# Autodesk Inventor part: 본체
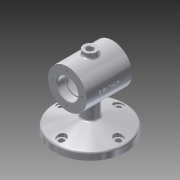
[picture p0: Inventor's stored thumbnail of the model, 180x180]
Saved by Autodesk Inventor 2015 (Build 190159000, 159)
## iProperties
Created: 2018-12
Part Number: 본체
Material: 알루미늄 6061
Document SubType Name: Modeling
Designer: now060
Density: 2.7 g/cm^3
Appearance: 알루미늄 - 평지
Mass: 685.037 g
Surface Area: 554.996 cm^2
Volume: 253.717 cm^3
Author: now060
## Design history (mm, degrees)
sketch "스케치7"
  geometry: C1 r 55 at (0, 0); 1 further point
  constraints: 1 centre point, 1 coincident
  dimensions: "d19" = 110 diameter of C1
extrude "돌출2" new body sketch "스케치7" distance "d20" = 11; taper "d21" = 0 deg
sketch "스케치8"
  geometry: C1 r 55 at (0, 0) reference; C2 r 12 at (0, 0)
  constraints: 1 centre point, 1 coincident
  dimensions: "d22" = 24 diameter of C2
extrude "돌출3" join sketch "스케치8" distance "d23" = 65; taper "d24" = 0 deg
sketch "스케치9"
  geometry: L1 (55, 11)-(55, 0) reference; L2 (55, 0)-(-55, 0) reference; L3 (-55, 0)-(-55, 11) reference; L4 (-55, 11)-(-12, 11) reference; L5 (-12, 11)-(-12, 76) reference; L6 (-12, 76)-(12, 76) reference; L7 (12, 76)-(12, 11) reference; L8 (12, 11)-(55, 11) reference; L9 (-35, 75)-(35, 75); L10 (35, 75)-(35, 105); L11 (35, 105)-(-35, 105); L12 (-35, 105)-(-35, 75); 3 further points
  constraints: 8 end point, 3 perpendicular, 2 midpoint, 1 horizontal, 1 vertical alignment
  dimensions: "d25" = 30 distance of L9.end L10.end; "d26" = 70 distance of L10.end L11.end; "d27" = 75 distance from line of L9 point (0, 0)
revolve "회전5" sketch "스케치9" stored, may be unused: angle "d28" = 90 deg
sketch "스케치10"
  geometry: L1 (55, 11)-(55, 0) reference; L2 (55, 0)-(-55, 0) reference; L3 (-55, 0)-(-55, 11) reference; L4 (-55, 11)-(-12, 11) reference; L5 (-12, 11)-(-12, 45) reference; L6 (-12, 45)-(-35, 45) reference; L7 (-35, 45)-(-35, 105) reference; L8 (-35, 105)-(35, 105) reference; L9 (35, 105)-(35, 45) reference; L10 (35, 45)-(12, 45) reference; L11 (12, 45)-(12, 11) reference; L12 (12, 11)-(55, 11) reference; L13 (-35, 45)-(-35, 105) reference; L14 (-35, 75)-(-23, 75); L15 (-23, 75)-(-23, 90.7); L16 (-23.3, 91)-(-35, 91); L17 (-35, 91)-(-35, 75); A1 r 0.3 centre (-23.3, 90.7) between (-23, 90.7) and (-23.3, 91); 2 further points
  constraints: 8 end point, 2 parallel, 2 point on circle, 2 point on line, 2 tangent, 1 centre point, 1 horizontal, 1 midpoint, 1 perpendicular
  dimensions: "d29" = 12 distance of point (-23, 91) L16.end; "d30" = 16 distance of L14.end point (-23, 91); "d31" = 0.3 radius of A1
revolve "회전6" sketch "스케치10" stored, may be unused: angle "d32" = 90 deg
sketch "스케치11"
  geometry: L1 (55, 11)-(55, 0) reference; L2 (55, 0)-(-55, 0) reference; L3 (-55, 0)-(-55, 11) reference; L4 (-55, 11)-(-12, 11) reference; L5 (-12, 11)-(-12, 45) reference; L6 (-12, 45)-(-35, 45) reference; L7 (-35, 45)-(-35, 59) reference; L8 (-35, 59)-(-23.3, 59) reference; L9 (-23, 59.3)-(-23, 90.7) reference; L10 (-23.3, 91)-(-35, 91) reference; L11 (-35, 91)-(-35, 105) reference; L12 (-35, 105)-(35, 105) reference; L13 (35, 105)-(35, 45) reference; L14 (35, 45)-(12, 45) reference; L15 (12, 45)-(12, 11) reference; L16 (12, 11)-(55, 11) reference; L17 (-23, 75)-(-20, 75); L18 (-20, 75)-(-20, 89); L19 (-20, 89)-(-23, 89); L20 (-23, 89)-(-23, 75); A1 r 0.3 centre (-23.3, 59.3) between (-23.3, 59) and (-23, 59.3) reference; A2 r 0.3 centre (-23.3, 90.7) between (-23, 90.7) and (-23.3, 91) reference; 1 further point
  constraints: 8 end point, 2 parallel, 1 horizontal, 1 midpoint, 1 perpendicular
  dimensions: "d33" = 3 distance of L18.end L19.end; "d34" = 14 distance of L17.end L18.end
revolve "회전7" sketch "스케치11" stored, may be unused: angle "d35" = 90 deg
sketch "스케치12"
  geometry: L1 (55, 11)-(55, 0) reference; L2 (55, 0)-(-55, 0) reference; L3 (-55, 0)-(-55, 11) reference; L4 (-55, 11)-(-12, 11) reference; L5 (-12, 11)-(-12, 45) reference; L6 (-12, 45)-(-35, 45) reference; L7 (-35, 45)-(-35, 59) reference; L8 (-35, 59)-(-23.3, 59) reference; L9 (-23, 59.3)-(-23, 61) reference; L10 (-23, 61)-(-20, 61) reference; L11 (-20, 61)-(-20, 89) reference; L12 (-20, 89)-(-23, 89) reference; L13 (-23, 89)-(-23, 90.7) reference; L14 (-23.3, 91)-(-35, 91) reference; L15 (-35, 91)-(-35, 105) reference; L16 (-35, 105)-(35, 105) reference; L17 (35, 105)-(35, 45) reference; L18 (35, 45)-(12, 45) reference; L19 (12, 45)-(12, 11) reference; L20 (12, 11)-(55, 11) reference; L21 (-20, 75)-(20, 75); L22 (20, 75)-(20, 97); L23 (17, 100)-(-17, 100); L24 (-20, 97)-(-20, 75); A1 r 0.3 centre (-23.3, 59.3) between (-23.3, 59) and (-23, 59.3) reference; A2 r 0.3 centre (-23.3, 90.7) between (-23, 90.7) and (-23.3, 91) reference; A3 r 3 centre (-17, 97) between (-17, 100) and (-20, 97); A4 r 3 centre (17, 97) between (20, 97) and (17, 100); 3 further points
  constraints: 8 end point, 4 point on circle, 4 point on line, 4 tangent, 2 centre point, 2 parallel, 1 equal radius, 1 horizontal, 1 midpoint, 1 perpendicular
  dimensions: "d36" = 40 distance of point (20, 100) point (-20, 100); "d37" = 25 distance of L21.end point (20, 100); "d38" = 3 radius of A3
revolve "회전8" sketch "스케치12" stored, may be unused: angle "d39" = 90 deg
sketch "스케치13"
  geometry: L1 (55, 11)-(55, 0) reference; L2 (55, 0)-(-55, 0) reference; L3 (-55, 0)-(-55, 11) reference; L4 (-55, 11)-(-12, 11) reference; L5 (-12, 11)-(-12, 45) reference; L6 (-12, 45)-(-35, 45) reference; L7 (-35, 45)-(-35, 59) reference; L8 (-35, 59)-(-23.3, 59) reference; L9 (-23, 59.3)-(-23, 61) reference; L10 (-23, 61)-(-20, 61) reference; L11 (-20, 61)-(-20, 53) reference; L12 (-17, 50)-(17, 50) reference; L13 (20, 53)-(20, 97) reference; L14 (17, 100)-(-17, 100) reference; L15 (-20, 97)-(-20, 89) reference; L16 (-20, 89)-(-23, 89) reference; L17 (-23, 89)-(-23, 90.7) reference; L18 (-23.3, 91)-(-35, 91) reference; L19 (-35, 91)-(-35, 105) reference; L20 (-35, 105)-(35, 105) reference; L21 (35, 105)-(35, 45) reference; L22 (35, 45)-(12, 45) reference; L23 (12, 45)-(12, 11) reference; L24 (12, 11)-(55, 11) reference; L25 (20, 75)-(23, 75); L26 (23, 75)-(23, 89); L27 (23, 89)-(20, 89); L28 (20, 89)-(20, 75); A1 r 0.3 centre (-23.3, 59.3) between (-23.3, 59) and (-23, 59.3) reference; A2 r 3 centre (-17, 53) between (-20, 53) and (-17, 50) reference; A3 r 3 centre (17, 53) between (17, 50) and (20, 53) reference; A4 r 3 centre (17, 97) between (20, 97) and (17, 100) reference; A5 r 3 centre (-17, 97) between (-17, 100) and (-20, 97) reference; A6 r 0.3 centre (-23.3, 90.7) between (-23, 90.7) and (-23.3, 91) reference; 1 further point
  constraints: 8 end point, 2 parallel, 1 horizontal, 1 midpoint, 1 perpendicular
  dimensions: "d40" = 3 distance of L26.end L27.end; "d41" = 14 distance of L25.end L26.end
revolve "회전9" sketch "스케치13" stored, may be unused: angle "d42" = 90 deg
sketch "스케치14"
  geometry: L1 (55, 11)-(55, 0) reference; L2 (55, 0)-(-55, 0) reference; L3 (-55, 0)-(-55, 11) reference; L4 (-55, 11)-(-12, 11) reference; L5 (-12, 11)-(-12, 45) reference; L6 (-12, 45)-(-35, 45) reference; L7 (-35, 45)-(-35, 59) reference; L8 (-35, 59)-(-23.3, 59) reference; L9 (-23, 59.3)-(-23, 61) reference; L10 (-23, 61)-(-20, 61) reference; L11 (-20, 61)-(-20, 53) reference; L12 (-17, 50)-(17, 50) reference; L13 (20, 53)-(20, 61) reference; L14 (20, 61)-(23, 61) reference; L15 (23, 61)-(23, 89) reference; L16 (23, 89)-(20, 89) reference; L17 (20, 89)-(20, 97) reference; L18 (17, 100)-(-17, 100) reference; L19 (-20, 97)-(-20, 89) reference; L20 (-20, 89)-(-23, 89) reference; L21 (-23, 89)-(-23, 90.7) reference; L22 (-23.3, 91)-(-35, 91) reference; L23 (-35, 91)-(-35, 105) reference; L24 (-35, 105)-(35, 105) reference; L25 (35, 105)-(35, 45) reference; L26 (35, 45)-(12, 45) reference; L27 (12, 45)-(12, 11) reference; L28 (12, 11)-(55, 11) reference; L29 (23, 89)-(23, 61) reference; L30 (23, 75)-(35, 75); L31 (35, 75)-(35, 91); L32 (35, 91)-(23.3, 91); L33 (23, 90.7)-(23, 75); A1 r 0.3 centre (-23.3, 59.3) between (-23.3, 59) and (-23, 59.3) reference; A2 r 3 centre (-17, 53) between (-20, 53) and (-17, 50) reference; A3 r 3 centre (17, 53) between (17, 50) and (20, 53) reference; A4 r 3 centre (17, 97) between (20, 97) and (17, 100) reference; A5 r 3 centre (-17, 97) between (-17, 100) and (-20, 97) reference; A6 r 0.3 centre (-23.3, 90.7) between (-23, 90.7) and (-23.3, 91) reference; A7 r 0.3 centre (23.3, 90.7) between (23.3, 91) and (23, 90.7); 2 further points
  constraints: 8 end point, 2 parallel, 2 point on circle, 2 point on line, 2 tangent, 1 centre point, 1 horizontal, 1 midpoint, 1 perpendicular
  dimensions: "d43" = 12 distance of L31.end point (23, 91); "d44" = 16 distance of point (23, 91) L30.start; "d45" = 0.3 radius of A7
revolve "회전10" sketch "스케치14" stored, may be unused: angle "d46" = 90 deg
sketch "스케치15" dims "d47" = 46
  geometry: C1 r 30 at (0, 0) reference; 3 further points
  constraints: 1 coincident, 1 vertical alignment, 2 other
hole "구멍1" sketch "스케치15" at (0, 23) diameter "d48" = 3.242; stored, may be unused: countersink angle "d52" = 90 deg, drill point angle "d54" = 118 deg; dims "d49" = 8, "d50" = 4, "d51" = 2, "d53" = 10
node "작업 평면1"
sketch "스케치16"
  geometry: C1 r 10 at (0, 0); 1 further point
  constraints: 1 centre point, 1 coincident
  dimensions: "d59" = 20 diameter of C1
extrude "돌출4" join sketch "스케치16" stored distance "d60" = 65; taper "d61" = 0 deg
sketch "스케치17"
  geometry: C1 r 10 at (0, 0) reference; C2 r 5 at (0, 0)
  constraints: 1 centre point, 1 coincident
  dimensions: "d62" = 10 diameter of C2
extrude "돌출5" cut sketch "스케치17" stored distance "d63" = 65; taper "d64" = 0 deg
fillet "모깎기1" dims "d65" = 3
chamfer "모따기1" distance "d66" = 1; stored, may be unused: second distance "d67" = 2, angle "d68" = 45 deg
node "작업축1"
sketch "스케치18"
  geometry: L1 (55, 11)-(-55, 11) reference; L2 (-55, 0)-(55, 0) reference; L3 (55, 11)-(-55, 11) reference; L4 (-55, 0)-(-55, 11) reference; L5 (0, 0)-(0, 112.228); L6 (-55, 11)-(0, 25.737); L7 (-55, 11)-(0, 11); L8 (0, 25.737)-(0, 11); L9 (0, 134.674)-(0, -22.446) reference
  constraints: 8 end point, 2 point on line, 2 vertical, 1 midpoint
  dimensions: "d70" = 75 deg angle of L4 L6
revolve "회전11" sketch "스케치18" stored, may be unused: angle "d71" = 90 deg
sketch "스케치19" dims "d72" = 88
  geometry: C1 r 55 at (0, 0) reference; C2 r 4.5 at (-44, 0); 1 further point
  constraints: 1 centre point, 1 coincident, 1 horizontal alignment, 2 other
  dimensions: "d73" = 9 diameter of C2
extrude "돌출6" cut sketch "스케치19" distance "d74" = 10; taper "d75" = 0 deg
sketch "스케치20"
  geometry: C1 r 4.5 at (0, 0) reference; C2 r 7 at (0, 0); 1 further point
  constraints: 1 centre point, 1 coincident
  dimensions: "d76" = 14 diameter of C2
extrude "돌출7" cut sketch "스케치20" distance "d77" = 10; taper "d78" = 0 deg
fillet "모깎기2" dims "d82" = 3
fillet "모깎기3" dims "d83" = 3
node "작업 평면2"
sketch "스케치21"
  geometry: L1 (-35, 45)-(-35, 105) reference; 2 further points
  constraints: 1 other
  dimensions: "d85" = 35 distance from line of L1 point (0, 75); "d86" = 30 vertical distance of L1.end point (0, 75)
feature "엠보싱1" sketch "스케치21" dims "d20" = 11, "d21" = 0, "d87" = 0.5, "d88" = 0
node "솔리드2"
pattern_circular "원형 패턴1" dims angle "d56" = 360 deg
mirror "대칭1"
pattern_circular "원형 패턴2" dims angle "d80" = 360 deg
node "투영된 루프1"
node "절단 모서리 투영6"
node "절단 모서리 투영7"
node "절단 모서리 투영8"
node "절단 모서리 투영9"
node "절단 모서리 투영10"
node "절단 모서리 투영11"
other parameters: "d58" = 112, "d84" = 31.25
